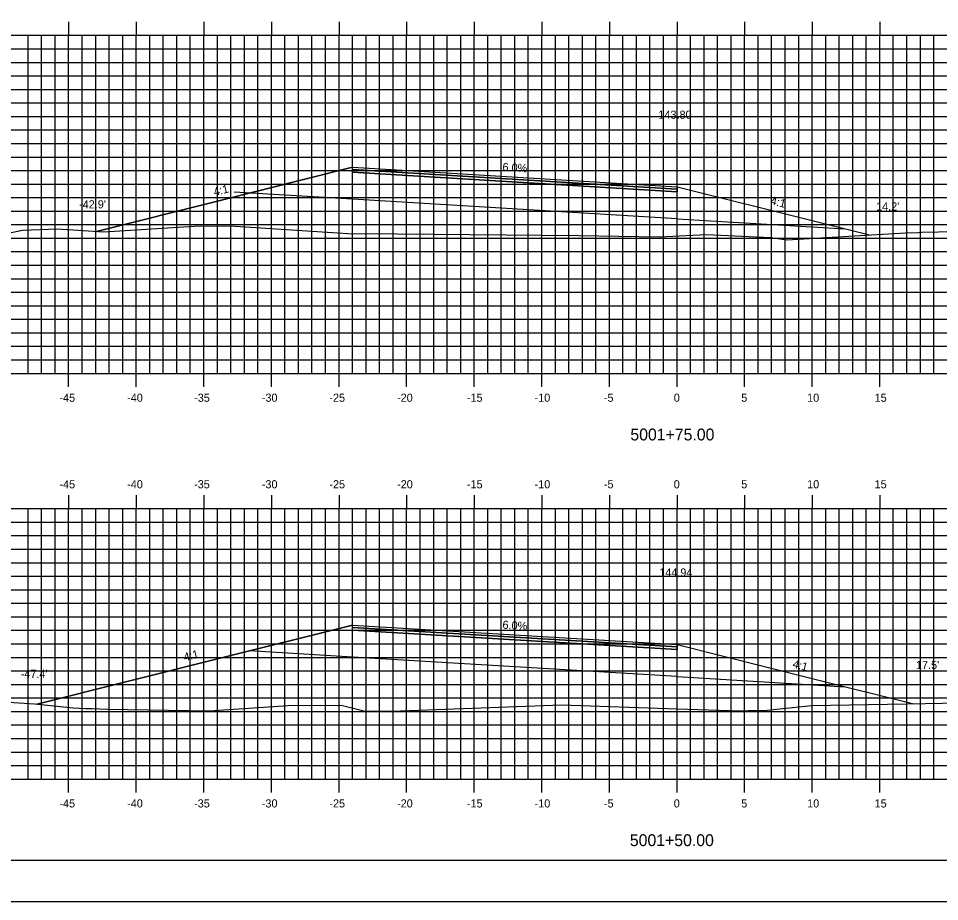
# Model space of a CAD drawing. Extents: x 851195 to 851367, y 365876 to 365986.
# Drawn here: x 851229.4 to 851297.6, y 365875.8 to 365941.1 of the extents above; entities that cross this region are included whole.
import ezdxf

# ---------------------------------------------------------------- set-up
doc = ezdxf.new("R2010")
doc.units = 0
for name, color, linetype in [('ANNOTATION', 7, 'Continuous'), ('BORDER', 7, 'Continuous'), ('D_Roadway_Centerline', 7, 'Continuous'), ('D_Roadway_Centerline_Text', 7, 'Continuous'), ('D_Roadway_Edge_TW', 7, 'Continuous'), ('D_Roadway_FinishedGrade', 7, 'Continuous'), ('D_Roadway_Pavement', 7, 'Continuous'), ('D_Roadway_SlopeLines', 7, 'Continuous'), ('D_Roadway_SubGrade', 7, 'Continuous'), ('D_Text_Standard', 7, 'Continuous'), ('H_V ANNOTATION', 7, 'Continuous'), ('MAJOR', 7, 'Continuous'), ('MINOR', 7, 'Continuous'), ('PLOT BOUNDARY', 7, 'Continuous'), ('S_Roadway_Centerline', 7, 'Continuous')]:
    doc.layers.add(name, color=color, linetype=linetype)

msp = doc.modelspace()

# ---------------------------------------------------------------- linework, layer by layer
at = {"layer": 'BORDER'}
msp.add_lwpolyline([(851203.142, 365878.833), (851363.142, 365878.833), (851363.142, 365983.833), (851203.142, 365983.833)], close=True, dxfattribs=at)
at = {"layer": 'D_Roadway_Centerline'}
for points in [[(851235.204, 365925.336), (851244.142, 365927.571), (851254.142, 365930.071), (851278.142, 365928.631), (851288.142, 365926.131), (851292.386, 365925.07)], [(851230.777, 365890.376), (851244.142, 365893.718), (851254.142, 365896.218), (851278.142, 365894.778), (851288.142, 365892.278), (851295.657, 365890.399)]]:
    msp.add_lwpolyline(points, dxfattribs=at)
at = {"layer": 'D_Roadway_Edge_TW'}
for points in [[(851254.142, 365930.071), (851278.142, 365928.631), (851278.142, 365928.464), (851254.142, 365929.904)], [(851254.142, 365896.218), (851278.142, 365894.778), (851278.142, 365894.611), (851254.142, 365896.051)]]:
    msp.add_lwpolyline(points, close=True, dxfattribs=at)
at = {"layer": 'D_Roadway_FinishedGrade'}
for p, q in [((851254.142, 365927.704), (851245.373, 365928.23)), ((851278.142, 365926.264), (851290.598, 365925.517)), ((851254.142, 365893.851), (851246.507, 365894.309)), ((851278.142, 365892.411), (851290.598, 365891.664))]:
    msp.add_line(p, q, dxfattribs=at)
at = {"layer": 'D_Roadway_Pavement'}
for points in [[(851254.142, 365929.904), (851278.142, 365928.464), (851278.142, 365928.264), (851254.142, 365929.704)], [(851254.142, 365896.051), (851278.142, 365894.611), (851278.142, 365894.411), (851254.142, 365895.851)]]:
    msp.add_lwpolyline(points, close=True, dxfattribs=at)
for points in [[(851278.142, 365928.464), (851278.142, 365928.264)], [(851278.142, 365928.464), (851278.142, 365928.264)], [(851278.142, 365894.611), (851278.142, 365894.411)], [(851278.142, 365894.611), (851278.142, 365894.411)]]:
    msp.add_lwpolyline(points, dxfattribs=at)
at = {"layer": 'D_Roadway_SlopeLines'}
for points in [[(851254.142, 365930.071), (851244.142, 365927.571), (851235.204, 365925.336)], [(851278.142, 365928.631), (851288.142, 365926.131), (851292.386, 365925.07)], [(851254.142, 365896.218), (851244.142, 365893.718), (851230.777, 365890.376)], [(851278.142, 365894.778), (851288.142, 365892.278), (851295.657, 365890.399)]]:
    msp.add_lwpolyline(points, dxfattribs=at)
at = {"layer": 'D_Roadway_SubGrade'}
for points in [[(851254.142, 365929.704), (851278.142, 365928.264)], [(851278.142, 365926.264), (851254.142, 365927.704)], [(851254.142, 365895.851), (851278.142, 365894.411)], [(851278.142, 365892.411), (851254.142, 365893.851)]]:
    msp.add_lwpolyline(points, dxfattribs=at)
at = {"layer": 'MAJOR'}
for p, q in [((851233.142, 365940.835), (851233.142, 365939.833)), ((851238.142, 365940.835), (851238.142, 365939.833)), ((851243.142, 365940.835), (851243.142, 365939.833)), ((851248.142, 365940.835), (851248.142, 365939.833)), ((851253.142, 365940.835), (851253.142, 365939.833)), ((851258.142, 365940.835), (851258.142, 365939.833)), ((851263.142, 365940.835), (851263.142, 365939.833)), ((851268.142, 365940.835), (851268.142, 365939.833)), ((851273.142, 365940.835), (851273.142, 365939.833)), ((851278.142, 365940.835), (851278.142, 365939.833)), ((851283.142, 365940.835), (851283.142, 365939.833)), ((851288.142, 365940.835), (851288.142, 365939.833)), ((851293.142, 365940.835), (851293.142, 365939.833)), ((851208.142, 365939.833), (851348.142, 365939.833)), ((851208.142, 365939.833), (851348.142, 365939.833)), ((851233.142, 365914.833), (851233.142, 365939.833)), ((851238.142, 365914.833), (851238.142, 365939.833)), ((851243.142, 365914.833), (851243.142, 365939.833)), ((851248.142, 365914.833), (851248.142, 365939.833)), ((851253.142, 365914.833), (851253.142, 365939.833)), ((851258.142, 365914.833), (851258.142, 365939.833)), ((851263.142, 365914.833), (851263.142, 365939.833)), ((851268.142, 365914.833), (851268.142, 365939.833)), ((851273.142, 365914.833), (851273.142, 365939.833)), ((851278.142, 365914.833), (851278.142, 365939.833)), ((851283.142, 365914.833), (851283.142, 365939.833)), ((851288.142, 365914.833), (851288.142, 365939.833)), ((851293.142, 365914.833), (851293.142, 365939.833)), ((851208.142, 365934.833), (851348.142, 365934.833)), ((851208.142, 365929.833), (851348.142, 365929.833)), ((851208.142, 365924.833), (851348.142, 365924.833)), ((851208.142, 365919.833), (851348.142, 365919.833)), ((851208.142, 365914.833), (851348.142, 365914.833)), ((851208.142, 365914.833), (851348.142, 365914.833)), ((851233.142, 365913.831), (851233.142, 365914.833)), ((851238.142, 365913.831), (851238.142, 365914.833)), ((851243.142, 365913.831), (851243.142, 365914.833)), ((851248.142, 365913.831), (851248.142, 365914.833)), ((851253.142, 365913.831), (851253.142, 365914.833)), ((851258.142, 365913.831), (851258.142, 365914.833)), ((851263.142, 365913.831), (851263.142, 365914.833)), ((851268.142, 365913.831), (851268.142, 365914.833)), ((851273.142, 365913.831), (851273.142, 365914.833)), ((851278.142, 365913.831), (851278.142, 365914.833)), ((851283.142, 365913.831), (851283.142, 365914.833)), ((851288.142, 365913.831), (851288.142, 365914.833)), ((851293.142, 365913.831), (851293.142, 365914.833)), ((851233.142, 365905.835), (851233.142, 365904.833)), ((851238.142, 365905.835), (851238.142, 365904.833)), ((851243.142, 365905.835), (851243.142, 365904.833)), ((851248.142, 365905.835), (851248.142, 365904.833)), ((851253.142, 365905.835), (851253.142, 365904.833)), ((851258.142, 365905.835), (851258.142, 365904.833)), ((851263.142, 365905.835), (851263.142, 365904.833)), ((851268.142, 365905.835), (851268.142, 365904.833)), ((851273.142, 365905.835), (851273.142, 365904.833)), ((851278.142, 365905.835), (851278.142, 365904.833)), ((851283.142, 365905.835), (851283.142, 365904.833)), ((851288.142, 365905.835), (851288.142, 365904.833)), ((851293.142, 365905.835), (851293.142, 365904.833)), ((851208.142, 365904.833), (851348.142, 365904.833)), ((851208.142, 365904.833), (851348.142, 365904.833)), ((851233.142, 365884.833), (851233.142, 365904.833)), ((851238.142, 365884.833), (851238.142, 365904.833)), ((851243.142, 365884.833), (851243.142, 365904.833)), ((851248.142, 365884.833), (851248.142, 365904.833)), ((851253.142, 365884.833), (851253.142, 365904.833)), ((851258.142, 365884.833), (851258.142, 365904.833)), ((851263.142, 365884.833), (851263.142, 365904.833)), ((851268.142, 365884.833), (851268.142, 365904.833)), ((851273.142, 365884.833), (851273.142, 365904.833)), ((851278.142, 365884.833), (851278.142, 365904.833)), ((851283.142, 365884.833), (851283.142, 365904.833)), ((851288.142, 365884.833), (851288.142, 365904.833)), ((851293.142, 365884.833), (851293.142, 365904.833)), ((851208.142, 365899.833), (851348.142, 365899.833)), ((851208.142, 365894.833), (851348.142, 365894.833)), ((851208.142, 365889.833), (851348.142, 365889.833)), ((851208.142, 365884.833), (851348.142, 365884.833)), ((851208.142, 365884.833), (851348.142, 365884.833)), ((851233.142, 365883.831), (851233.142, 365884.833)), ((851238.142, 365883.831), (851238.142, 365884.833)), ((851243.142, 365883.831), (851243.142, 365884.833)), ((851248.142, 365883.831), (851248.142, 365884.833)), ((851253.142, 365883.831), (851253.142, 365884.833)), ((851258.142, 365883.831), (851258.142, 365884.833)), ((851263.142, 365883.831), (851263.142, 365884.833)), ((851268.142, 365883.831), (851268.142, 365884.833)), ((851273.142, 365883.831), (851273.142, 365884.833)), ((851278.142, 365883.831), (851278.142, 365884.833)), ((851283.142, 365883.831), (851283.142, 365884.833)), ((851288.142, 365883.831), (851288.142, 365884.833)), ((851293.142, 365883.831), (851293.142, 365884.833))]:
    msp.add_line(p, q, dxfattribs=at)
at = {"layer": 'MINOR'}
for p, q in [((851230.142, 365914.833), (851230.142, 365939.833)), ((851231.142, 365914.833), (851231.142, 365939.833)), ((851232.142, 365914.833), (851232.142, 365939.833)), ((851234.142, 365914.833), (851234.142, 365939.833)), ((851235.142, 365914.833), (851235.142, 365939.833)), ((851236.142, 365914.833), (851236.142, 365939.833)), ((851237.142, 365914.833), (851237.142, 365939.833)), ((851239.142, 365914.833), (851239.142, 365939.833)), ((851240.142, 365914.833), (851240.142, 365939.833)), ((851241.142, 365914.833), (851241.142, 365939.833)), ((851242.142, 365914.833), (851242.142, 365939.833)), ((851244.142, 365914.833), (851244.142, 365939.833)), ((851245.142, 365914.833), (851245.142, 365939.833)), ((851246.142, 365914.833), (851246.142, 365939.833)), ((851247.142, 365914.833), (851247.142, 365939.833)), ((851249.142, 365914.833), (851249.142, 365939.833)), ((851250.142, 365914.833), (851250.142, 365939.833)), ((851251.142, 365914.833), (851251.142, 365939.833)), ((851252.142, 365914.833), (851252.142, 365939.833)), ((851254.142, 365914.833), (851254.142, 365939.833)), ((851255.142, 365914.833), (851255.142, 365939.833)), ((851256.142, 365914.833), (851256.142, 365939.833)), ((851257.142, 365914.833), (851257.142, 365939.833)), ((851259.142, 365914.833), (851259.142, 365939.833)), ((851260.142, 365914.833), (851260.142, 365939.833)), ((851261.142, 365914.833), (851261.142, 365939.833)), ((851262.142, 365914.833), (851262.142, 365939.833)), ((851264.142, 365914.833), (851264.142, 365939.833)), ((851265.142, 365914.833), (851265.142, 365939.833)), ((851266.142, 365914.833), (851266.142, 365939.833)), ((851267.142, 365914.833), (851267.142, 365939.833)), ((851269.142, 365914.833), (851269.142, 365939.833)), ((851270.142, 365914.833), (851270.142, 365939.833)), ((851271.142, 365914.833), (851271.142, 365939.833)), ((851272.142, 365914.833), (851272.142, 365939.833)), ((851274.142, 365914.833), (851274.142, 365939.833)), ((851275.142, 365914.833), (851275.142, 365939.833)), ((851276.142, 365914.833), (851276.142, 365939.833)), ((851277.142, 365914.833), (851277.142, 365939.833)), ((851279.142, 365914.833), (851279.142, 365939.833)), ((851280.142, 365914.833), (851280.142, 365939.833)), ((851281.142, 365914.833), (851281.142, 365939.833)), ((851282.142, 365914.833), (851282.142, 365939.833)), ((851284.142, 365914.833), (851284.142, 365939.833)), ((851285.142, 365914.833), (851285.142, 365939.833)), ((851286.142, 365914.833), (851286.142, 365939.833)), ((851287.142, 365914.833), (851287.142, 365939.833)), ((851289.142, 365914.833), (851289.142, 365939.833)), ((851290.142, 365914.833), (851290.142, 365939.833)), ((851291.142, 365914.833), (851291.142, 365939.833)), ((851292.142, 365914.833), (851292.142, 365939.833)), ((851294.142, 365914.833), (851294.142, 365939.833)), ((851295.142, 365914.833), (851295.142, 365939.833)), ((851296.142, 365914.833), (851296.142, 365939.833)), ((851297.142, 365914.833), (851297.142, 365939.833)), ((851208.142, 365938.833), (851348.142, 365938.833)), ((851208.142, 365937.833), (851348.142, 365937.833)), ((851208.142, 365936.833), (851348.142, 365936.833)), ((851208.142, 365935.833), (851348.142, 365935.833)), ((851208.142, 365933.833), (851348.142, 365933.833)), ((851208.142, 365932.833), (851348.142, 365932.833)), ((851208.142, 365931.833), (851348.142, 365931.833)), ((851208.142, 365930.833), (851348.142, 365930.833)), ((851208.142, 365928.833), (851348.142, 365928.833)), ((851208.142, 365927.833), (851348.142, 365927.833)), ((851208.142, 365926.833), (851348.142, 365926.833)), ((851208.142, 365925.833), (851348.142, 365925.833)), ((851208.142, 365923.833), (851348.142, 365923.833)), ((851208.142, 365922.833), (851348.142, 365922.833)), ((851208.142, 365921.833), (851348.142, 365921.833)), ((851208.142, 365920.833), (851348.142, 365920.833)), ((851208.142, 365918.833), (851348.142, 365918.833)), ((851208.142, 365917.833), (851348.142, 365917.833)), ((851208.142, 365916.833), (851348.142, 365916.833)), ((851208.142, 365915.833), (851348.142, 365915.833)), ((851230.142, 365884.833), (851230.142, 365904.833)), ((851231.142, 365884.833), (851231.142, 365904.833)), ((851232.142, 365884.833), (851232.142, 365904.833)), ((851234.142, 365884.833), (851234.142, 365904.833)), ((851235.142, 365884.833), (851235.142, 365904.833)), ((851236.142, 365884.833), (851236.142, 365904.833)), ((851237.142, 365884.833), (851237.142, 365904.833)), ((851239.142, 365884.833), (851239.142, 365904.833)), ((851240.142, 365884.833), (851240.142, 365904.833)), ((851241.142, 365884.833), (851241.142, 365904.833)), ((851242.142, 365884.833), (851242.142, 365904.833)), ((851244.142, 365884.833), (851244.142, 365904.833)), ((851245.142, 365884.833), (851245.142, 365904.833)), ((851246.142, 365884.833), (851246.142, 365904.833)), ((851247.142, 365884.833), (851247.142, 365904.833)), ((851249.142, 365884.833), (851249.142, 365904.833)), ((851250.142, 365884.833), (851250.142, 365904.833)), ((851251.142, 365884.833), (851251.142, 365904.833)), ((851252.142, 365884.833), (851252.142, 365904.833)), ((851254.142, 365884.833), (851254.142, 365904.833)), ((851255.142, 365884.833), (851255.142, 365904.833)), ((851256.142, 365884.833), (851256.142, 365904.833)), ((851257.142, 365884.833), (851257.142, 365904.833)), ((851259.142, 365884.833), (851259.142, 365904.833)), ((851260.142, 365884.833), (851260.142, 365904.833)), ((851261.142, 365884.833), (851261.142, 365904.833)), ((851262.142, 365884.833), (851262.142, 365904.833)), ((851264.142, 365884.833), (851264.142, 365904.833)), ((851265.142, 365884.833), (851265.142, 365904.833)), ((851266.142, 365884.833), (851266.142, 365904.833)), ((851267.142, 365884.833), (851267.142, 365904.833)), ((851269.142, 365884.833), (851269.142, 365904.833)), ((851270.142, 365884.833), (851270.142, 365904.833)), ((851271.142, 365884.833), (851271.142, 365904.833)), ((851272.142, 365884.833), (851272.142, 365904.833)), ((851274.142, 365884.833), (851274.142, 365904.833)), ((851275.142, 365884.833), (851275.142, 365904.833)), ((851276.142, 365884.833), (851276.142, 365904.833)), ((851277.142, 365884.833), (851277.142, 365904.833)), ((851279.142, 365884.833), (851279.142, 365904.833)), ((851280.142, 365884.833), (851280.142, 365904.833)), ((851281.142, 365884.833), (851281.142, 365904.833)), ((851282.142, 365884.833), (851282.142, 365904.833)), ((851284.142, 365884.833), (851284.142, 365904.833)), ((851285.142, 365884.833), (851285.142, 365904.833)), ((851286.142, 365884.833), (851286.142, 365904.833)), ((851287.142, 365884.833), (851287.142, 365904.833)), ((851289.142, 365884.833), (851289.142, 365904.833)), ((851290.142, 365884.833), (851290.142, 365904.833)), ((851291.142, 365884.833), (851291.142, 365904.833)), ((851292.142, 365884.833), (851292.142, 365904.833)), ((851294.142, 365884.833), (851294.142, 365904.833)), ((851295.142, 365884.833), (851295.142, 365904.833)), ((851296.142, 365884.833), (851296.142, 365904.833)), ((851297.142, 365884.833), (851297.142, 365904.833)), ((851208.142, 365903.833), (851348.142, 365903.833)), ((851208.142, 365902.833), (851348.142, 365902.833)), ((851208.142, 365901.833), (851348.142, 365901.833)), ((851208.142, 365900.833), (851348.142, 365900.833)), ((851208.142, 365898.833), (851348.142, 365898.833)), ((851208.142, 365897.833), (851348.142, 365897.833)), ((851208.142, 365896.833), (851348.142, 365896.833)), ((851208.142, 365895.833), (851348.142, 365895.833)), ((851208.142, 365893.833), (851348.142, 365893.833)), ((851208.142, 365892.833), (851348.142, 365892.833)), ((851208.142, 365891.833), (851348.142, 365891.833)), ((851208.142, 365890.833), (851348.142, 365890.833)), ((851208.142, 365888.833), (851348.142, 365888.833)), ((851208.142, 365887.833), (851348.142, 365887.833)), ((851208.142, 365886.833), (851348.142, 365886.833)), ((851208.142, 365885.833), (851348.142, 365885.833))]:
    msp.add_line(p, q, dxfattribs=at)
at = {"layer": 'PLOT BOUNDARY'}
msp.add_lwpolyline([(851195.049, 365875.774), (851365.049, 365875.774), (851365.049, 365985.774), (851195.049, 365985.774)], close=True, dxfattribs=at)
at = {"layer": 'S_Roadway_Centerline'}
for points in [[(851208.142, 365926.314), (851215.041, 365926.007), (851217.958, 365925.881), (851219.79, 365925.455), (851220.465, 365924.815), (851223.262, 365924.724), (851227.308, 365924.921), (851229.726, 365925.418), (851232.295, 365925.52), (851235.754, 365925.302), (851242.416, 365925.714), (851245.078, 365925.751), (851253.803, 365925.182), (851257.459, 365925.158), (851270.86, 365925.023), (851276.825, 365924.935), (851280.32, 365925.09), (851285.065, 365924.889), (851286.257, 365924.7), (851295.049, 365925.23), (851296.011, 365925.262), (851296.222, 365925.276), (851305.027, 365925.458)], [(851225.59, 365890.713), (851230.612, 365890.393), (851233.478, 365890.111), (851234.425, 365890.046), (851234.886, 365890.046), (851236.026, 365890.002), (851243.533, 365889.875), (851249.371, 365890.264), (851252.716, 365890.287), (851253.023, 365890.285), (851253.295, 365890.292), (851255.074, 365889.864), (851257.696, 365889.884), (851269.595, 365890.325), (851278.151, 365890.024), (851282.754, 365889.872), (851283.395, 365889.891), (851284.806, 365889.931), (851288.087, 365890.28), (851296.52, 365890.412), (851301.569, 365890.522)]]:
    msp.add_lwpolyline(points, dxfattribs=at)

# ---------------------------------------------------------------- texts
at = {"layer": 'ANNOTATION'}
for s, rotation, p in [('6.0%', 356.56637, (851265.219, 365929.808)), ('4:1', 14.03624, (851243.941, 365927.951)), ('4:1', 345.96376, (851285.017, 365927.343)), ('6.0%', 356.56637, (851265.219, 365895.955)), ('4:1', 14.03624, (851241.727, 365893.545)), ('4:1', 345.96376, (851286.652, 365893.081))]:
    msp.add_text(s, height=0.6, rotation=rotation, dxfattribs=at).set_placement(p)
at = {"layer": 'D_Roadway_Centerline_Text'}
for s, p in [('143.80', (851276.767, 365933.663)), ('144.94', (851276.826, 365899.81))]:
    msp.add_text(s, height=0.6, dxfattribs=at).set_placement(p)
at = {"layer": 'D_Text_Standard'}
for s, p in [("-42.9'", (851233.914, 365927.033)), ("14.2'", (851292.869, 365926.874)), ("17.5'", (851295.817, 365892.968)), ("-47.4'", (851229.597, 365892.313))]:
    msp.add_text(s, height=0.6, dxfattribs=at).set_placement(p)
at = {"layer": 'H_V ANNOTATION'}
for s, height, p in [('-45', 0.6, (851232.46, 365912.733)), ('-40', 0.6, (851237.468, 365912.733)), ('-35', 0.6, (851242.422, 365912.733)), ('-30', 0.6, (851247.43, 365912.733)), ('-25', 0.6, (851252.427, 365912.733)), ('-20', 0.6, (851257.435, 365912.733)), ('-15', 0.6, (851262.599, 365912.733)), ('-10', 0.6, (851267.607, 365912.733)), ('-5', 0.6, (851272.732, 365912.733)), ('0', 0.6, (851277.901, 365912.733)), ('5', 0.6, (851282.893, 365912.733)), ('10', 0.6, (851287.767, 365912.733)), ('15', 0.6, (851292.759, 365912.733)), ('5001+75.00', 0.875, (851274.693, 365909.876)), ('-45', 0.6, (851232.46, 365906.333)), ('-40', 0.6, (851237.468, 365906.333)), ('-35', 0.6, (851242.422, 365906.333)), ('-30', 0.6, (851247.43, 365906.333)), ('-25', 0.6, (851252.427, 365906.333)), ('-20', 0.6, (851257.435, 365906.333)), ('-15', 0.6, (851262.599, 365906.333)), ('-10', 0.6, (851267.607, 365906.333)), ('-5', 0.6, (851272.732, 365906.333)), ('0', 0.6, (851277.901, 365906.333)), ('5', 0.6, (851282.893, 365906.333)), ('10', 0.6, (851287.767, 365906.333)), ('15', 0.6, (851292.759, 365906.333)), ('-45', 0.6, (851232.46, 365882.733)), ('-40', 0.6, (851237.468, 365882.733)), ('-35', 0.6, (851242.422, 365882.733)), ('-30', 0.6, (851247.43, 365882.733)), ('-25', 0.6, (851252.427, 365882.733)), ('-20', 0.6, (851257.435, 365882.733)), ('-15', 0.6, (851262.599, 365882.733)), ('-10', 0.6, (851267.607, 365882.733)), ('-5', 0.6, (851272.732, 365882.733)), ('0', 0.6, (851277.901, 365882.733)), ('5', 0.6, (851282.893, 365882.733)), ('10', 0.6, (851287.767, 365882.733)), ('15', 0.6, (851292.759, 365882.733)), ('5001+50.00', 0.875, (851274.654, 365879.876))]:
    msp.add_text(s, height=height, dxfattribs=at).set_placement(p)

doc.saveas('drawing.dxf')
